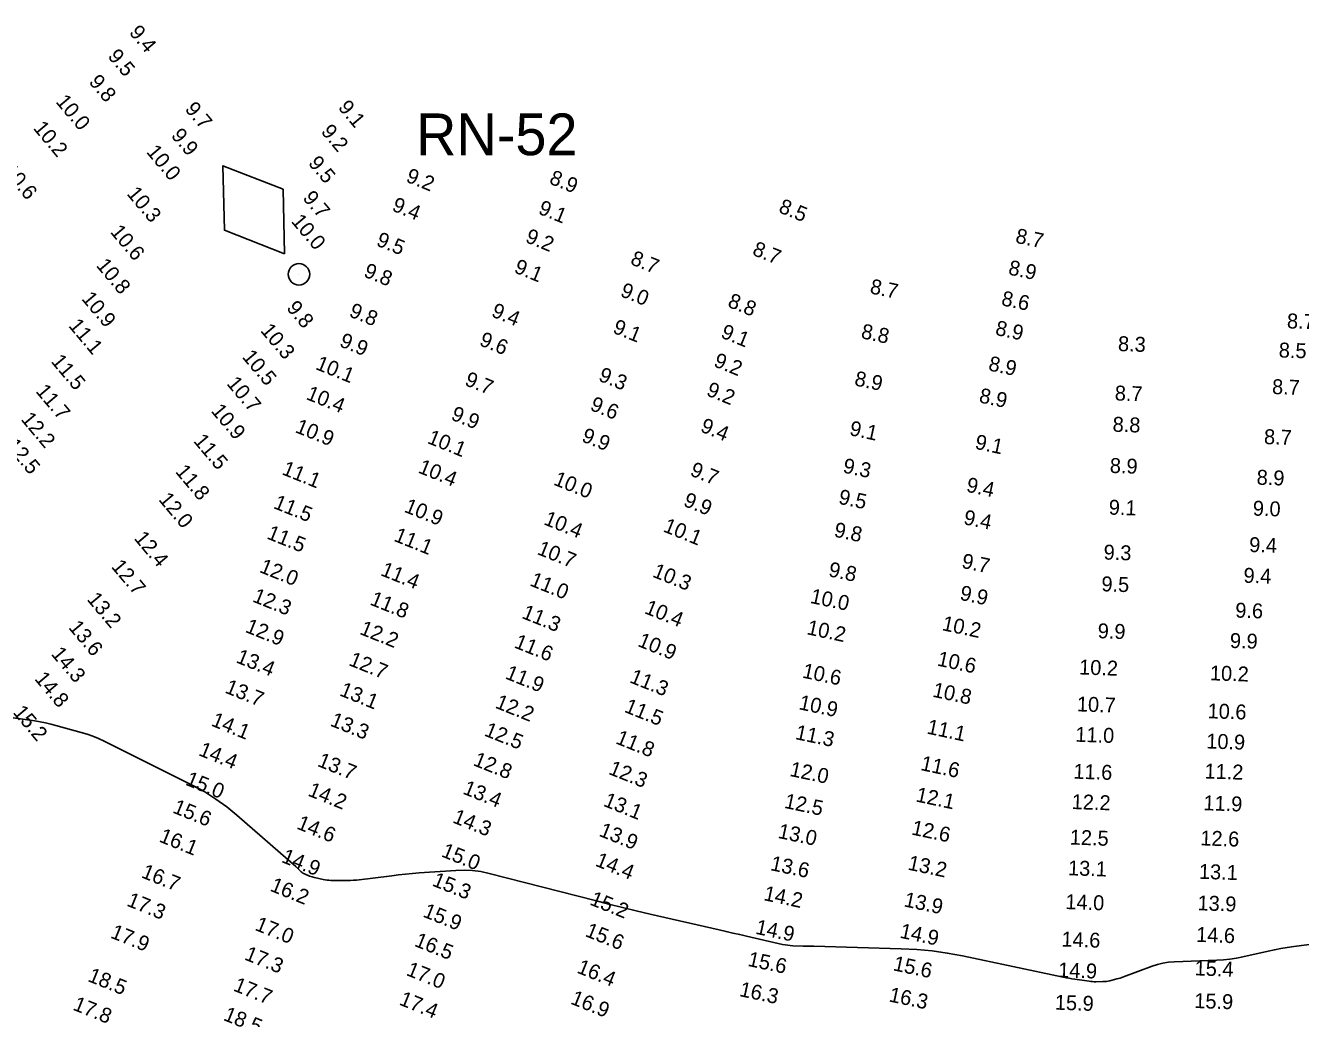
# Model space of a CAD drawing. Extents: x 988130 to 1132882, y 654656 to 841453.
# Drawn here: x 1068858.7 to 1069285.8, y 733786.1 to 734118.9 of the extents above; entities that cross this region are included whole.
import ezdxf

# ---------------------------------------------------------------- set-up
doc = ezdxf.new("R2010")
doc.units = 0
for name, color, linetype in [('Default', 7, 'Continuous'), ('V-CHAN-NAID', 7, 'Continuous'), ('V-TOPO-MAJR', 7, 'Continuous'), ('V-TOPO-SOUN', 7, 'Continuous')]:
    doc.layers.add(name, color=color, linetype=linetype)

# ---------------------------------------------------------------- blocks, each defined once
blk = doc.blocks.new('POINT_DISPLAY')
at = {"layer": 'Default'}
blk.add_line((0, 0), (0, 0), dxfattribs=at)

msp = doc.modelspace()

# ---------------------------------------------------------------- linework, layer by layer
at = {"layer": 'V-CHAN-NAID'}
msp.add_lwpolyline([(1068945.46, 734042.4), (1068944.97, 734064.03), (1068924.81, 734071.89), (1068925.31, 734050.26)], close=True, dxfattribs=at)
msp.add_circle((1068950.28, 734035.52), 3.6, dxfattribs=at)
at = {"layer": 'V-TOPO-MAJR'}
msp.add_lwpolyline([(1069315.92, 733814.35), (1069283.57, 733810.22), (1069281.41, 733809.92), (1069279.26, 733809.56), (1069277.12, 733809.16), (1069274.99, 733808.7), (1069266.48, 733806.77), (1069264.35, 733806.34), (1069262.2, 733806.01), (1069260.04, 733805.79), (1069257.87, 733805.66), (1069243.48, 733805.17), (1069241.59, 733805.02), (1069239.73, 733804.73), (1069237.9, 733804.29), (1069236.1, 733803.7), (1069226.51, 733800.1), (1069225.95, 733799.9), (1069225.39, 733799.71), (1069224.83, 733799.54), (1069224.26, 733799.39), (1069221.95, 733798.81), (1069221.38, 733798.68), (1069220.81, 733798.59), (1069220.23, 733798.53), (1069219.65, 733798.51), (1069217.32, 733798.48), (1069216.73, 733798.48), (1069216.15, 733798.51), (1069215.57, 733798.56), (1069214.99, 733798.63), (1069210.26, 733799.32), (1069209.28, 733799.46), (1069208.3, 733799.63), (1069207.33, 733799.81), (1069206.36, 733800.01), (1069172.58, 733807.12), (1069167.5, 733808.07), (1069162.39, 733808.79), (1069157.25, 733809.28), (1069152.08, 733809.53), (1069122.74, 733810.33), (1069121.87, 733810.36), (1069121, 733810.38), (1069120.13, 733810.41), (1069119.26, 733810.43), (1069115.78, 733810.54), (1069114.91, 733810.59), (1069114.05, 733810.68), (1069113.19, 733810.81), (1069112.34, 733810.98), (1069100.27, 733813.72), (1069097.98, 733814.24), (1069095.68, 733814.77), (1069093.39, 733815.29), (1069091.1, 733815.82), (1069067.94, 733821.15), (1069063.32, 733822.23), (1069058.71, 733823.34), (1069054.1, 733824.48), (1069049.5, 733825.64), (1069013.98, 733834.76), (1069011.23, 733835.35), (1069008.47, 733835.71), (1069005.68, 733835.85), (1069002.88, 733835.76), (1068990.62, 733834.9), (1068988.31, 733834.72), (1068986, 733834.51), (1068983.69, 733834.27), (1068981.39, 733834), (1068969.53, 733832.54), (1068968.55, 733832.44), (1068967.57, 733832.37), (1068966.59, 733832.34), (1068965.6, 733832.34), (1068960.98, 733832.42), (1068960.33, 733832.45), (1068959.7, 733832.5), (1068959.06, 733832.59), (1068958.43, 733832.71), (1068955.48, 733833.35), (1068955.07, 733833.45), (1068954.67, 733833.57), (1068954.27, 733833.7), (1068953.87, 733833.86), (1068952.12, 733834.6), (1068951.83, 733834.73), (1068951.57, 733834.89), (1068951.32, 733835.08), (1068951.08, 733835.29), (1068950.19, 733836.19), (1068949.96, 733836.41), (1068949.73, 733836.63), (1068949.5, 733836.84), (1068949.26, 733837.05), (1068929.52, 733854.28), (1068926.07, 733857.1), (1068922.47, 733859.69), (1068918.7, 733862.05), (1068914.78, 733864.17), (1068885.06, 733879.06), (1068883.18, 733879.94), (1068881.28, 733880.73), (1068879.33, 733881.42), (1068877.35, 733882.01), (1068868.88, 733884.34), (1068867.12, 733884.79), (1068865.34, 733885.2), (1068863.55, 733885.54), (1068861.75, 733885.83), (1068854.53, 733886.89)], dxfattribs=at)

# ---------------------------------------------------------------- block references
at = {"layer": 'V-CHAN-NAID', "xscale": 0.32808398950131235, "yscale": 0.32808398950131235}
msp.add_blockref('POINT_DISPLAY', (1068950.28, 734035.52), dxfattribs=at)

# ---------------------------------------------------------------- texts
at = {"layer": 'V-CHAN-NAID'}
msp.add_text('RN-52', height=14, dxfattribs=at).set_placement((1068989.52, 734075.41))
at = {"layer": 'V-TOPO-SOUN'}
for s, rotation, p in [('9.4', 310, (1068893.16, 734116.44)), ('9.5', 310, (1068886, 734108.45)), ('9.8', 310, (1068879.66, 734099.88)), ('10.0 ', 310, (1068868.58, 734093.25)), ('9.1', 310, (1068963.16, 734091.32)), ('9.7', 310, (1068911.84, 734090.76)), ('10.2 ', 310, (1068861.04, 734084.38)), ('9.2', 310, (1068957.44, 734083.22)), ('9.9', 310, (1068907.2, 734081.9)), ('10.0 ', 310, (1068898.94, 734076.42)), ('10.6 ', 310, (1068850.84, 734070.03)), ('9.5', 310, (1068953.17, 734072.64)), ('9.2', 338, (1068985.81, 734066.66)), ('8.9', 338, (1069033.84, 734066.03)), ('10.3 ', 310, (1068892.38, 734062.41)), ('9.7', 310, (1068951.31, 734060.97)), ('9.4', 338, (1068981.16, 734056.95)), ('9.1', 338, (1069030.15, 734055.93)), ('8.5', 338, (1069110.68, 734056.4)), ('10.0 ', 310, (1068947.46, 734053.19)), ('10.6 ', 310, (1068886.84, 734049.62)), ('8.7', 348, (1069190.09, 734046.13)), ('9.5', 338, (1068975.87, 734045.28)), ('9.2', 338, (1069025.84, 734046.4)), ('8.7', 338, (1069061.02, 734039.02)), ('8.7', 338, (1069101.89, 734042.14)), ('10.8 ', 310, (1068882.12, 734038.37)), ('9.8', 338, (1068971.67, 734034.86)), ('9.1', 338, (1069022.08, 734036.22)), ('8.9', 348, (1069187.71, 734035.5)), ('8.7', 348, (1069141.34, 734029.19)), ('9.0', 338, (1069057.63, 734028.3)), ('8.6', 348, (1069185.37, 734025.18)), ('10.9 ', 310, (1068877.21, 734027.24)), ('9.8', 310, (1068945.88, 734024.12)), ('9.8', 338, (1068966.79, 734021.49)), ('9.4', 338, (1069014.46, 734021.49)), ('8.8', 338, (1069093.61, 734024.76)), ('8.7', 358, (1069281.25, 734017.42)), ('11.1 ', 310, (1068872.85, 734018.18)), ('10.3 ', 310, (1068937.17, 734016.55)), ('9.1', 338, (1069055.12, 734016.04)), ('9.1', 338, (1069091.33, 734014.42)), ('8.8', 348, (1069138.37, 734014.15)), ('8.9', 348, (1069183.34, 734015.25)), ('9.9', 338, (1068963.56, 734011.47)), ('9.6', 338, (1069010.42, 734011.83)), ('8.3', 358, (1069224.63, 734009.81)), ('8.5', 358, (1069278.5, 734007.67)), ('11.5 ', 310, (1068867.01, 734006.23)), ('10.5 ', 310, (1068931.02, 734007.74)), ('9.2', 338, (1069088.93, 734004.79)), ('10.1 ', 338, (1068955.54, 734003.82)), ('9.3', 338, (1069050.34, 733999.97)), ('8.9', 348, (1069181.04, 734003.35)), ('10.7 ', 310, (1068925.83, 733998.79)), ('9.7', 338, (1069005.52, 733998.48)), ('8.9', 348, (1069136.15, 733998.33)), ('8.7', 358, (1069276.26, 733995.4)), ('11.7 ', 310, (1068861.88, 733996.22)), ('10.4 ', 338, (1068952.38, 733993.76)), ('9.2', 338, (1069086.48, 733995.04)), ('8.9', 348, (1069177.9, 733992.63)), ('8.7', 358, (1069223.56, 733993.26)), ('10.9 ', 310, (1068920.62, 733989.63)), ('9.9', 338, (1069000.91, 733986.93)), ('9.6', 338, (1069047.52, 733990.16)), ('12.2 ', 310, (1068856.91, 733986.85)), ('9.4', 338, (1069084.47, 733982.94)), ('8.8', 358, (1069222.84, 733982.79)), ('10.9 ', 338, (1068948.72, 733982.68)), ('10.1 ', 338, (1068993, 733979.04)), ('9.9', 338, (1069044.67, 733979.65)), ('9.1', 348, (1069134.5, 733981.66)), ('8.7', 358, (1069273.56, 733978.64)), ('12.5 ', 310, (1068851.82, 733978.01)), ('11.5 ', 310, (1068914.73, 733979.55)), ('9.1', 348, (1069176.53, 733977.09)), ('8.9', 358, (1069221.9, 733968.98)), ('11.8 ', 310, (1068908.65, 733969.29)), ('11.1 ', 338, (1068944.27, 733968.58)), ('10.4 ', 338, (1068989.92, 733969.15)), ('9.7', 338, (1069081.01, 733968.22)), ('9.3', 348, (1069132.28, 733969.12)), ('8.9', 358, (1069271.1, 733965.04)), ('10.0 ', 338, (1069035.26, 733965.1)), ('9.4', 348, (1069173.63, 733962.71)), ('12.0 ', 310, (1068903.04, 733959.94)), ('11.5 ', 338, (1068941.44, 733957.24)), ('9.9', 338, (1069078.78, 733958.03)), ('9.5', 348, (1069130.81, 733958.69)), ('10.9 ', 338, (1068985.24, 733956.01)), ('9.1', 358, (1069221.55, 733955)), ('9.0', 358, (1069269.81, 733954.67)), ('10.4 ', 338, (1069032, 733951.81)), ('10.1 ', 338, (1069072.01, 733949.42)), ('9.4', 348, (1069172.71, 733951.83)), ('12.4 ', 310, (1068894.81, 733946.95)), ('11.5 ', 338, (1068939.21, 733947.05)), ('11.1 ', 338, (1068981.78, 733946.26)), ('9.8', 348, (1069129.3, 733947.66)), ('10.7 ', 338, (1069029.79, 733941.83)), ('9.3', 358, (1069219.81, 733939.95)), ('9.4', 358, (1069268.59, 733942.47)), ('12.0 ', 338, (1068936.74, 733935.82)), ('9.7', 348, (1069172.06, 733937.2)), ('12.7 ', 310, (1068887.18, 733937.46)), ('11.4 ', 338, (1068977.35, 733934.75)), ('10.3 ', 338, (1069068.43, 733934.26)), ('9.8', 348, (1069127.45, 733934.37)), ('9.4', 358, (1069266.69, 733932.18)), ('11.0 ', 338, (1069027.33, 733931.32)), ('9.9', 348, (1069171.46, 733926.49)), ('9.5', 358, (1069219.08, 733929.32)), ('13.2 ', 310, (1068879.03, 733926.51)), ('12.3 ', 338, (1068934.43, 733925.94)), ('11.8 ', 338, (1068973.77, 733924.92)), ('10.0 ', 348, (1069121.33, 733925.43)), ('11.3 ', 338, (1069024.64, 733920.42)), ('10.4 ', 338, (1069065.75, 733922.04)), ('9.6', 358, (1069263.93, 733920.5)), ('13.6 ', 310, (1068872.85, 733917.08)), ('12.9 ', 338, (1068931.99, 733915.75)), ('12.2 ', 338, (1068970.31, 733915.07)), ('10.2 ', 348, (1069120.19, 733914.93)), ('10.2 ', 348, (1069165.48, 733916.3)), ('9.9', 358, (1069217.84, 733913.59)), ('11.6 ', 338, (1069022.1, 733910.55)), ('10.9 ', 338, (1069063.47, 733911.03)), ('9.9', 358, (1069262.13, 733910.34)), ('14.3 ', 310, (1068867.03, 733908.2)), ('13.4 ', 338, (1068928.89, 733905.56)), ('12.7 ', 338, (1068966.67, 733904.62)), ('10.6 ', 348, (1069163.87, 733904.44)), ('10.2 ', 358, (1069211.61, 733901.44)), ('14.8 ', 310, (1068861.47, 733899.88)), ('11.9 ', 338, (1069019.1, 733900.15)), ('11.3 ', 338, (1069060.76, 733898.87)), ('10.6 ', 348, (1069118.69, 733900.41)), ('10.2 ', 358, (1069255.43, 733899.48)), ('13.7 ', 338, (1068925.18, 733895.41)), ('13.1 ', 338, (1068963.58, 733894.49)), ('10.8 ', 348, (1069162.33, 733894)), ('12.2 ', 338, (1069015.73, 733890.35)), ('11.5 ', 338, (1069059, 733888.96)), ('10.9 ', 348, (1069117.52, 733889.8)), ('10.7 ', 358, (1069210.86, 733889.07)), ('15.2 ', 310, (1068854.26, 733888.61)), ('10.6 ', 358, (1069254.65, 733886.76)), ('14.1 ', 338, (1068920.57, 733884.36)), ('13.3 ', 338, (1068960.44, 733884.35)), ('12.5 ', 338, (1069012.08, 733881.03)), ('11.3 ', 348, (1069116.33, 733879.8)), ('11.1 ', 348, (1069160.41, 733881.65)), ('11.8 ', 338, (1069056.09, 733878.41)), ('11.0 ', 358, (1069210.35, 733878.9)), ('10.9 ', 358, (1069254.21, 733876.65)), ('14.4 ', 338, (1068916.37, 733874.44)), ('13.7 ', 338, (1068956.18, 733870.83)), ('12.8 ', 338, (1069008.37, 733871.08)), ('12.3 ', 338, (1069053.72, 733868.17)), ('12.0 ', 348, (1069114.47, 733867.45)), ('11.6 ', 348, (1069158.31, 733869.42)), ('11.6 ', 358, (1069209.7, 733866.52)), ('11.2 ', 358, (1069253.62, 733866.59)), ('15.0 ', 338, (1068911.96, 733864.53)), ('14.2 ', 338, (1068952.98, 733860.91)), ('13.4 ', 338, (1069004.88, 733861.56)), ('12.1 ', 348, (1069156.71, 733858.9)), ('15.6 ', 338, (1068907.67, 733855.21)), ('13.1 ', 338, (1069051.99, 733857.47)), ('12.5 ', 348, (1069112.63, 733856.76)), ('12.2 ', 358, (1069209.13, 733856.34)), ('11.9 ', 358, (1069253.26, 733855.94)), ('14.3 ', 338, (1069001.45, 733851.92)), ('14.6 ', 338, (1068949.24, 733849.85)), ('13.9 ', 338, (1069050.52, 733847.41)), ('13.0 ', 348, (1069110.51, 733846.69)), ('12.6 ', 348, (1069155.25, 733847.83)), ('16.1 ', 338, (1068903.12, 733845.5)), ('12.5 ', 358, (1069208.49, 733844.44)), ('12.6 ', 358, (1069252.24, 733844.17)), ('14.9 ', 338, (1068944.13, 733838.64)), ('15.0 ', 338, (1068997.69, 733840.53)), ('16.7 ', 338, (1068897.16, 733833.52)), ('14.4 ', 338, (1069049.27, 733837.41)), ('13.6 ', 348, (1069107.98, 733835.89)), ('13.2 ', 348, (1069154.05, 733836.06)), ('13.1 ', 358, (1069207.9, 733834.15)), ('13.1 ', 358, (1069251.75, 733832.97)), ('16.2 ', 338, (1068940.3, 733829.02)), ('15.3 ', 338, (1068994.62, 733830.76)), ('14.2 ', 348, (1069105.73, 733825.83)), ('17.3 ', 338, (1068892.3, 733824.02)), ('15.2 ', 338, (1069047.41, 733824.4)), ('13.9 ', 348, (1069152.72, 733823.75)), ('14.0 ', 358, (1069207.01, 733822.82)), ('13.9 ', 358, (1069251.28, 733822.42)), ('15.9 ', 338, (1068991.51, 733820.36)), ('17.9 ', 338, (1068886.85, 733813.31)), ('17.0 ', 338, (1068935.23, 733815.89)), ('15.6 ', 338, (1069045.88, 733813.83)), ('14.9 ', 348, (1069103, 733814.56)), ('14.9 ', 348, (1069151.35, 733813.24)), ('14.6 ', 358, (1069250.82, 733811.83)), ('16.5 ', 338, (1068988.66, 733810.54)), ('14.6 ', 358, (1069205.7, 733810.28)), ('17.3 ', 338, (1068931.74, 733805.99)), ('15.6 ', 348, (1069100.4, 733803.8)), ('17.0 ', 338, (1068985.94, 733800.77)), ('16.4 ', 338, (1069043.1, 733801.59)), ('15.6 ', 348, (1069149.11, 733802.32)), ('14.9 ', 358, (1069204.6, 733799.96)), ('15.4 ', 358, (1069250.32, 733800.61)), ('18.5 ', 338, (1068879.24, 733798.75)), ('17.7 ', 338, (1068927.99, 733795.57)), ('17.4 ', 338, (1068983.56, 733790.88)), ('16.9 ', 338, (1069040.99, 733791.18)), ('16.3 ', 348, (1069097.62, 733793.68)), ('16.3 ', 348, (1069147.72, 733791.89)), ('15.9 ', 358, (1069250.2, 733789.67)), ('17.8 ', 338, (1068874.24, 733789.15)), ('15.9 ', 358, (1069203.48, 733789.11)), ('18.5 ', 338, (1068924.66, 733785.7))]:
    msp.add_text(s, height=5, rotation=rotation, dxfattribs=at).set_placement(p)

doc.saveas('drawing.dxf')
